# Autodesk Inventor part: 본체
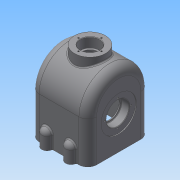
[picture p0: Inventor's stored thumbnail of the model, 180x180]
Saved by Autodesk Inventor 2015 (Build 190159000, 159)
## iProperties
Created: 2023-03
Part Number: 본체
Material: 일반
Document SubType Name: Modeling
Designer: home
Density: 1 g/cm^3
Appearance: 기본값
Author: home
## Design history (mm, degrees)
sketch "스케치1"
  geometry: L1 (-70, 0)-(-70, -94); L2 (-70, -94)-(70, -94); L3 (70, -94)-(70, 0); A1 r 70 centre (0, 0) between (70, 0) and (-70, 0); 1 further point
  constraints: 6 end point, 2 perpendicular, 2 point on circle, 2 tangent, 1 centre point, 1 coincident, 1 vertical
  dimensions: "d0" = 140 diameter of A1; "d1" = 94 distance from line of L2 point (0, 0)
extrude "돌출1" new body sketch "스케치1" stored distance "d2" = 130; taper "d3" = 0 deg
fillet "모깎기1" dims "d4" = 20
feature "쉘1" dims "d5" = 10
sketch "스케치2"
  geometry: L1 (94, -50)-(94, 50) reference; C1 r 40 at (19, 0); 1 further point
  constraints: 1 centre point, 1 horizontal alignment
  dimensions: "d6" = 80 diameter of C1; "d7" = 75 distance from line of C1.centre L1
extrude "돌출2" cut sketch "스케치2" distance "d8" = 2; taper "d9" = 0 deg
node "작업 평면1"
sketch "스케치3"
  geometry: L1 (-94, -50)-(-94, 50) reference; C1 r 30 at (-19, 0); 1 further point
  constraints: 1 centre point, 1 horizontal alignment
  dimensions: "d11" = 75 distance from line of C1.centre L1; "d12" = 60 diameter of C1
extrude "돌출3" join sketch "스케치3" distance "d13" = 12; taper "d14" = 45 deg
sketch "스케치4"
  geometry: C1 r 40 at (0, 0) reference; C2 r 26 at (0, 0); 1 further point
  constraints: 1 centre point, 1 coincident
  dimensions: "d15" = 52 diameter of C2
extrude "돌출4" cut sketch "스케치4" distance "d16" = 18; taper "d17" = 0 deg
sketch "스케치5"
  geometry: C1 r 26 at (0, 0) reference; C2 r 23 at (0, 0); 1 further point
  constraints: 1 centre point, 1 coincident
  dimensions: "d18" = 46 diameter of C2
extrude "돌출5" cut sketch "스케치5" distance "d19" = 18; taper "d20" = 0 deg
sketch "스케치6"
  geometry: L1 (0, 0)-(-30, 0); C1 r 26 at (0, 0) reference; 1 further point
  constraints: 2 end point, 1 horizontal
  dimensions: "d21" = 30 distance of L1.start L1.end
hole "구멍1" sketch "스케치6" at (-30, 0) diameter "d22" = 3.242; stored, may be unused: countersink angle "d26" = 90 deg, drill point angle "d28" = 118 deg; dims "d23" = 8, "d24" = 4, "d25" = 2, "d27" = 10
node "작업 평면2"
sketch "스케치7"
  geometry: C1 r 35 at (45, -70); 1 further point
  constraints: 1 centre point, 1 coincident
  dimensions: "d33" = 70 diameter of C1
extrude "돌출6" join sketch "스케치7" stored distance "d34" = 18; taper "d35" = 0 deg
sketch "스케치8"
  geometry: C1 r 21.5 at (0, 0); 1 further point
  constraints: 1 centre point, 1 coincident
  dimensions: "d36" = 43 diameter of C1
extrude "돌출7" cut sketch "스케치8" distance "d37" = 22; taper "d38" = 0 deg
sketch "스케치9"
  geometry: C1 r 17 at (0, 0); 1 further point
  constraints: 1 centre point, 1 coincident
  dimensions: "d39" = 34 diameter of C1
extrude "돌출8" cut sketch "스케치9" distance "d40" = 22; taper "d41" = 0 deg
sketch "스케치10"
  geometry: L1 (0, 0)-(-26, 0)
  constraints: 2 end point, 1 horizontal
  dimensions: "d42" = 26 distance of L1.start L1.end
hole "구멍2" sketch "스케치10" at (-26, 0) diameter "d43" = 3.242; stored, may be unused: countersink angle "d47" = 90 deg, drill point angle "d49" = 118 deg; dims "d44" = 8, "d45" = 4, "d46" = 2, "d48" = 10
sketch "스케치11"
  geometry: L1 (0, -140)-(90, -140) reference; A1 r 12 centre (18, -140) between (6, -140) and (30, -140); 1 further point
  constraints: 2 point on circle, 2 point on line, 1 centre point, 1 horizontal alignment
  dimensions: "d53" = 24 diameter of A1; "d54" = 27 horizontal distance of A1.centre point (45, -70)
extrude "돌출9" join sketch "스케치11" distance "d55" = 40; taper "d56" = 0 deg
fillet "모깎기2" dims "d57" = 12
hole "구멍3" diameter "d60" = 10.106; stored, may be unused: countersink angle "d64" = 90 deg, drill point angle "d66" = 118 deg; dims "d58" = 10, "d59" = 10, "d61" = 24, "d62" = 4, "d63" = 2, "d65" = 26
hole "구멍4" diameter "d69" = 10.106; stored, may be unused: countersink angle "d73" = 90 deg, drill point angle "d75" = 118 deg; dims "d67" = 10, "d68" = 10, "d70" = 24, "d71" = 4, "d72" = 2, "d74" = 26
hole "구멍5" diameter "d78" = 10.106; stored, may be unused: countersink angle "d82" = 90 deg, drill point angle "d84" = 118 deg; dims "d76" = 10, "d77" = 10, "d79" = 24, "d80" = 4, "d81" = 2, "d83" = 26
hole "구멍6" diameter "d87" = 10.106; stored, may be unused: countersink angle "d91" = 90 deg, drill point angle "d93" = 118 deg; dims "d85" = 10, "d86" = 10, "d88" = 24, "d89" = 4, "d90" = 2, "d92" = 26
chamfer "모따기1" distance "d94" = 1; stored, may be unused: second distance "d95" = 2, angle "d96" = 45 deg
fillet "모깎기3" dims "d97" = 1
sketch "스케치12"
  geometry: L1 (-15, -94)-(15, -94) reference; L2 (22.5, 84)-(-22.5, 84) reference; 3 further points
  constraints: 1 midpoint, 1 vertical alignment, 1 other
  dimensions: "d98" = 8 distance from line of point (0, 76) L2
feature "엠보싱1" sketch "스케치12" dims "d0" = 140, "d1" = 94, "d99" = 0.5, "d100" = 0
fillet "모깎기4" dims "d101" = 3
fillet "모깎기5" dims "d102" = 3
fillet "모깎기6" dims "d103" = 3
node "솔리드1"
pattern_circular "원형 패턴1" dims angle "d30" = 360 deg
mirror "대칭1"
pattern_circular "원형 패턴2" dims angle "d51" = 360 deg
mirror "대칭2"
mirror "대칭3"
other parameters: "d10" = 12, "d32" = -178
